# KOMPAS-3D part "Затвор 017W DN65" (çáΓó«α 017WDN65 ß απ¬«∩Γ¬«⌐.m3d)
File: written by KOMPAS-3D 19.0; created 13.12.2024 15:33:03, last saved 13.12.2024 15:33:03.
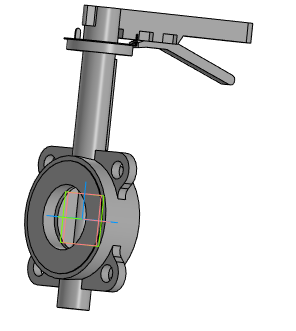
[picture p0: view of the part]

Document properties: Автор: Евгений; Полное имя файла: ..\Затвор 017WDN65.a3d

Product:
- Part/product: Затвор 017W DN65
    Масса: 5.87019

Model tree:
1. Операция без истории:1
